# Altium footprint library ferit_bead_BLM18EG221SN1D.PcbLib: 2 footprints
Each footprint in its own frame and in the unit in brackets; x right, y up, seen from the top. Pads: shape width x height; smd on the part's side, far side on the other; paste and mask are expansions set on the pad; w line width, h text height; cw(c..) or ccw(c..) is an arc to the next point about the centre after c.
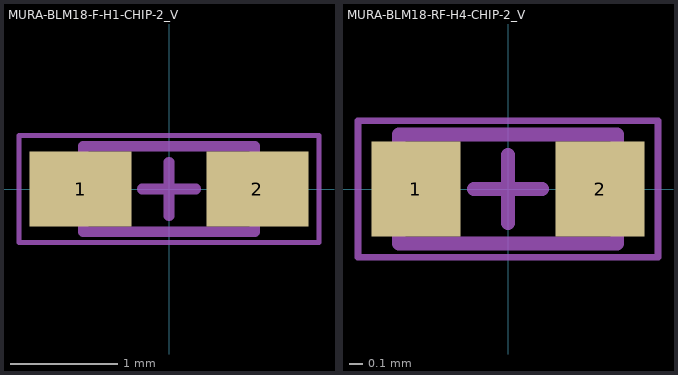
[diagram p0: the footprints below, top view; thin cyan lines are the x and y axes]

## MURA-BLM18-F-H1-CHIP-2_V [mm] "Chip Ferrite Bead, 2-Leads, Body 1.6x0.8mm, Height 0.95mm, Flow"
height 0.95
pads (2):
  rect 0.95x0.7 smd: 1(-0.825,0) 2(0.825,0)
Mechanical 6:
  text "Land Pattern Adapted for Flow Soldering" at -1,0.6 h0.05
Mechanical 13:
  lines w0.1: -0.8,-0.4 -0.8,0.4 0.8,0.4 0.8,-0.4 -0.8,-0.4
Mechanical 15:
  lines w0.05: -1.4,-0.5 1.4,-0.5 1.4,0.5 -1.4,0.5 -1.4,-0.5
  lines w0.1: -0.25,0 0.25,0 ; 0,-0.25 0,0.25
3D body: height 0.95, standoff 0, extent -0.8,-0.4 0.8,0.4

## MURA-BLM18-RF-H4-CHIP-2_V [mm] "Chip Ferrite Bead, 2-Leads, Body 1.6x0.8mm, Height 0.95mm, Reflow"
height 0.95
pads (2):
  rect 0.65x0.7 smd: 1(-0.675,0) 2(0.675,0)
Mechanical 6:
  text "Land Pattern Adapted for Reflow Soldering" at -1,0.6 h0.05
Mechanical 13:
  lines w0.1: -0.8,-0.4 -0.8,0.4 0.8,0.4 0.8,-0.4 -0.8,-0.4
Mechanical 15:
  lines w0.05: -1.1,-0.5 1.1,-0.5 1.1,0.5 -1.1,0.5 -1.1,-0.5
  lines w0.1: -0.25,0 0.25,0 ; 0,-0.25 0,0.25
3D body: height 0.95, standoff 0, extent -0.8,-0.4 0.8,0.4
